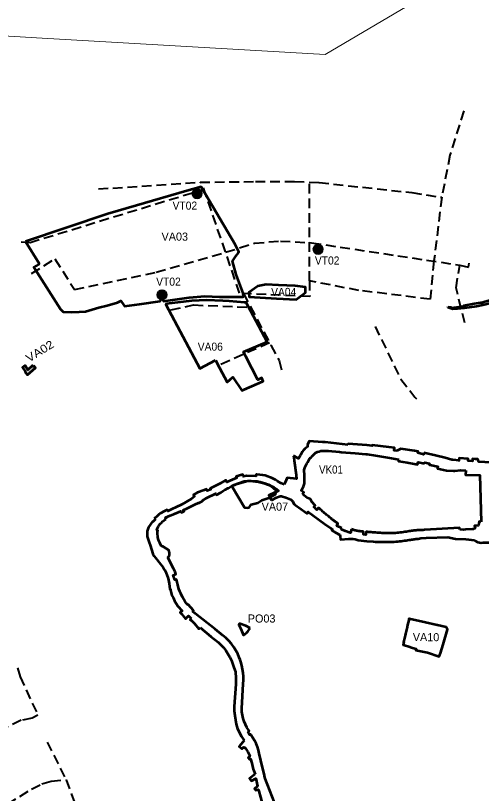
# Model space of a CAD drawing. Extents: x -650145 to -642675, y -1074338 to -1066803.
# Drawn here: x -647799 to -646647, y -1071056 to -1069131 of the extents above; entities that cross this region are included whole.
import ezdxf

# ---------------------------------------------------------------- set-up
doc = ezdxf.new("R2010")
doc.units = 0
doc.header["$LTSCALE"] = 8
doc.linetypes.add('MEDIUM_DASHED', pattern=[4.5, 3, -1.5])
for name, color, linetype, lineweight in [('12', 7, 'MEDIUM_DASHED', 40), ('15', 7, 'Continuous', 13), ('20', 7, 'Continuous', 13), ('44', 7, 'Continuous', 53), ('53', 7, 'Continuous', 53), ('55', 7, 'Continuous', 53), ('60', 7, 'Continuous', 53)]:
    doc.layers.add(name, color=color, linetype=linetype, lineweight=lineweight)
for name, color, linetype in [('17', 7, 'Continuous'), ('3', 7, 'Continuous'), ('56', 7, 'Continuous'), ('8', 7, 'Continuous')]:
    doc.layers.add(name, color=color, linetype=linetype)

msp = doc.modelspace()

# ---------------------------------------------------------------- hatches: boundary and pattern name
at = {"layer": '15'}
for points in [[(-647338.289, -1069571.583, 1), (-647361.814, -1069571.583, 1)], [(-647038.994, -1069709.305, 1), (-647062.519, -1069709.305, 1)], [(-647425.058, -1069822.133, 1), (-647448.583, -1069822.133, 1)]]:
    msp.add_hatch(color=256, dxfattribs=at).paths.add_polyline_path(points)
at = {"layer": '60'}
msp.add_hatch(color=256, dxfattribs=at).paths.add_polyline_path([(-647753.96, -1069997.9), (-647755.37, -1069999.17), (-647757.35, -1069996.96), (-647768.87, -1070007.32), (-647775.67, -1069996.86), (-647781.47, -1070001.96), (-647774.7, -1070012.64), (-647775.34, -1070013.22), (-647769.35, -1070019.98), (-647749.87, -1070002.45)])

# ---------------------------------------------------------------- linework, layer by layer
at = {"layer": '12'}
for p, q in [((-647072.241, -1069787.533), (-647072.241, -1069543.185)), ((-647291.307, -1069993.228), (-647170.84, -1069940.165)), ((-647720.463, -1070929.111), (-647674.039, -1071022.323))]:
    msp.add_line(p, q, dxfattribs=at)
for points in [[(-646690.349, -1069366.515), (-646724.478, -1069476.486), (-646744.903, -1069580.656)], [(-647594.109, -1069559.949), (-647342.265, -1069543.531), (-647205.182, -1069541.582), (-647108.806, -1069541.669), (-647047.983, -1069544.191), (-646818.857, -1069568.917), (-646744.903, -1069580.656), (-646763.998, -1069737.618), (-646773.775, -1069832.942), (-646949.668, -1069811.025), (-647072.241, -1069787.533), (-647071.353, -1069826.293), (-647244.785, -1069818.042), (-647338.767, -1069543.481)], [(-647785.07, -1069690.63), (-647763.238, -1069692.321), (-647332.905, -1069560.606)], [(-647279.5, -1069716.624), (-647208.318, -1069694.158), (-647143.504, -1069688.843), (-647066.866, -1069693.057), (-646699.975, -1069748.527), (-646678.869, -1069753.112), (-646676.91, -1069743.82)], [(-647759.613, -1069769.184), (-647701.982, -1069733.103), (-647653.087, -1069809.089), (-647451.321, -1069765.984), (-647279.5, -1069716.624)], [(-646687.702, -1069891.186), (-646709.186, -1069804.667), (-646700.4, -1069748.435)], [(-647235.467, -1069818.485), (-647167.428, -1069946.59), (-647147.296, -1069984.626), (-647140.3, -1070010.7)], [(-647414.535, -1069859.089), (-647358.559, -1069846.998), (-647217.195, -1069852.888)], [(-646909.766, -1069900.481), (-646846.095, -1070030.546), (-646811.614, -1070075.327), (-646807.189, -1070079.418)], [(-647794.16, -1070745.19), (-647787.83, -1070767.157), (-647743.987, -1070862.016), (-647758.284, -1070869.702), (-647784.836, -1070875.103), (-647850.393, -1070906.456), (-647898.698, -1070936.31), (-647903.521, -1070987.043), (-648287.54, -1071265.293)], [(-647818.707, -1071082.607), (-647759.543, -1071045.17), (-647733.735, -1071032.504), (-647710.774, -1071025.971), (-647674.039, -1071022.323), (-647646.98, -1071094.735)]]:
    msp.add_lwpolyline(points, dxfattribs=at)
at = {"layer": '15', "lineweight": 35}
for centre in [(-647350.051, -1069571.583), (-647050.756, -1069709.305), (-647436.82, -1069822.133)]:
    msp.add_circle(centre, 11.762, dxfattribs=at)
at = {"layer": '20'}
msp.add_lwpolyline([(-649263.719, -1069096.97), (-648650.963, -1069132.769), (-648341.578, -1069150.909), (-648022.16, -1069169.54), (-647733.165, -1069186.38), (-647403.931, -1069205.68), (-647033.327, -1069227.251), (-646738.287, -1069051.902)], dxfattribs=at)
at = {"layer": '44'}
msp.add_line((-646729.54, -1069853.69), (-646729.24, -1069851.41), dxfattribs=at)
for points in [[(-646515.63, -1069810.24), (-646522.32, -1069812.28), (-646560.92, -1069825.33), (-646613.65, -1069840.02), (-646620.06, -1069841.69), (-646629.83, -1069844.23), (-646635.93, -1069845.82), (-646658.5, -1069850.59), (-646689.73, -1069854.58), (-646705.87, -1069856.62), (-646717.66, -1069857.11), (-646729.54, -1069853.69)], [(-646729.24, -1069851.41), (-646723.5, -1069852.83), (-646719.82, -1069853.78), (-646689.63, -1069849.7), (-646689.8, -1069848.71), (-646664.22, -1069843.72), (-646648.18, -1069841.04), (-646648.28, -1069841.78), (-646638.34, -1069838.73), (-646623.31, -1069834.1)]]:
    msp.add_lwpolyline(points, dxfattribs=at)
at = {"layer": '53'}
msp.add_line((-647421.838, -1070473.735), (-647422.635, -1070472.518), dxfattribs=at)
for points in [[(-647039.387, -1070186.449), (-647072.923, -1070184.24), (-647076.809, -1070193), (-647076.809, -1070197.855), (-647079.337, -1070199.774), (-647083.246, -1070203.107), (-647086.798, -1070206.819), (-647089.955, -1070210.872), (-647094.562, -1070218.473), (-647099.29, -1070227.11), (-647111.87, -1070220.205)], [(-646976.875, -1070193.507), (-647032.82, -1070186.854), (-647039.387, -1070186.449)], [(-646855.781, -1070208.078), (-646862.711, -1070206.961), (-646861.74, -1070201.031), (-646875.455, -1070198.795), (-646916.636, -1070194.129), (-646916.861, -1070195.418), (-646929.734, -1070194.175), (-646930.298, -1070194.121), (-646976.601, -1070190.623), (-646976.875, -1070193.507)], [(-647111.87, -1070220.205), (-647110.98, -1070225.11), (-647110.039, -1070232.112), (-647109.285, -1070237.98)], [(-647082.83, -1070247.64), (-647081.36, -1070244.56), (-647078.582, -1070239.619), (-647076.458, -1070235.94), (-647070.915, -1070226.315), (-647067.989, -1070224.388), (-647065.283, -1070221.423), (-647064.18, -1070220.24), (-647060.499, -1070216.29), (-647056.707, -1070213.102), (-647052.28, -1070210.94), (-647047.968, -1070209.58), (-647043.59, -1070208.45), (-647035.36, -1070207.72), (-647025.027, -1070208.36), (-647016.667, -1070208.977), (-647006.834, -1070209.85), (-646997.5, -1070210.678), (-646993.691, -1070211.016), (-646958.739, -1070214.119), (-646932.512, -1070216.446), (-646929.525, -1070216.711), (-646908.791, -1070219.988), (-646868.816, -1070226.259), (-646851.139, -1070229.271)], [(-646788.988, -1070213.082), (-646789.87, -1070216.844), (-646803.79, -1070213.3), (-646802.956, -1070209.992), (-646812.428, -1070207.897), (-646845.679, -1070203.387), (-646855.781, -1070208.078)], [(-646717.674, -1070230.771), (-646719.944, -1070230.462), (-646736.508, -1070225.129), (-646760.066, -1070219.479), (-646788.988, -1070213.082)], [(-647109.285, -1070237.98), (-647106.03, -1070261.928), (-647105.074, -1070267.762), (-647104.579, -1070271.34), (-647104.079, -1070276.135), (-647104.378, -1070277.278), (-647127.044, -1070274.833), (-647131.716, -1070286.148), (-647134.186, -1070291.454)], [(-646851.139, -1070229.271), (-646851.793, -1070233.722), (-646830.617, -1070236.834), (-646813.3, -1070240.207), (-646804.487, -1070241.739), (-646803.291, -1070236.491), (-646787.53, -1070239.695)], [(-646787.53, -1070239.695), (-646786.78, -1070237.23), (-646775.43, -1070239.05), (-646775.88, -1070242.132), (-646774.542, -1070242.367), (-646754.132, -1070247.152), (-646755.192, -1070251.673), (-646732.744, -1070256.936), (-646715.68, -1070257.99), (-646712.338, -1070257.99), (-646698.729, -1070255.707), (-646685.341, -1070256.642)], [(-646593.751, -1070236.292), (-646594.226, -1070230.306), (-646619.339, -1070231.28), (-646617.731, -1070236.951), (-646623.104, -1070237.199), (-646653.044, -1070235.3), (-646655.238, -1070229.03), (-646661.949, -1070228.719), (-646668.506, -1070228.289), (-646668.854, -1070233.592), (-646679.445, -1070232.801), (-646679.103, -1070227.593), (-646701.794, -1070226.105), (-646702.125, -1070232.096), (-646702.089, -1070232.106), (-646717.674, -1070230.771)], [(-647089.327, -1070315.412), (-647086.02, -1070311.465), (-647092.921, -1070306.47), (-647090.471, -1070303.079), (-647087.003, -1070296.218), (-647085.126, -1070291.49), (-647084.541, -1070288.586), (-647084.007, -1070279.103), (-647084.542, -1070269.458), (-647085.139, -1070254.958), (-647083.753, -1070250.537), (-647082.83, -1070247.64)], [(-646685.341, -1070256.642), (-646686.113, -1070267.707), (-646650.247, -1070268.194), (-646646.892, -1070384.01)], [(-647227.638, -1070270.39), (-647235.663, -1070271.253), (-647236.556, -1070266.274), (-647252.994, -1070271.911), (-647251.55, -1070274.71), (-647268.639, -1070282.251)], [(-647134.186, -1070291.454), (-647142.537, -1070288.389), (-647151.169, -1070282.796), (-647156.431, -1070279.561), (-647165.727, -1070275.049), (-647170.603, -1070272.893), (-647175.301, -1070271.298), (-647181.491, -1070269.375), (-647187.15, -1070268.533), (-647194.921, -1070267.565), (-647202.22, -1070267.01), (-647204.18, -1070266.838), (-647204.893, -1070270.725), (-647227.638, -1070270.39)], [(-647335.663, -1070331.862), (-647336.33, -1070330.63), (-647325.666, -1070324.301), (-647303.599, -1070313.877), (-647301.753, -1070317.414), (-647291.355, -1070311.289), (-647291.55, -1070310.93), (-647285.393, -1070307.326), (-647285.626, -1070306.782), (-647280.817, -1070303.954), (-647280.52, -1070304.49), (-647274.32, -1070300.9), (-647274.046, -1070301.209), (-647263.777, -1070295.135), (-647259.22, -1070292.91), (-647256.375, -1070291.915), (-647253.6, -1070290.787), (-647224.25, -1070282.597)], [(-647292.693, -1070288.731), (-647305.843, -1070295.204), (-647317.56, -1070301.06), (-647316.143, -1070304.037), (-647324.803, -1070306.737), (-647325.346, -1070305.444)], [(-647268.639, -1070282.251), (-647276.777, -1070285.465), (-647278.788, -1070280.86), (-647292.693, -1070288.731)], [(-647224.25, -1070282.597), (-647216.198, -1070282.153), (-647201.74, -1070283.3), (-647194.11, -1070285.023), (-647182.735, -1070288.44), (-647173.41, -1070291.46), (-647165.68, -1070295.43), (-647160.5, -1070297.72), (-647154.219, -1070302.228), (-647148.592, -1070306.848), (-647171.459, -1070317.591)], [(-647325.346, -1070305.444), (-647326.68, -1070303.115), (-647332.811, -1070305.203), (-647348.647, -1070311.42), (-647359.257, -1070316.77), (-647356.197, -1070321.392), (-647364.164, -1070326.958), (-647387.944, -1070341.049), (-647403.193, -1070348.394), (-647411.024, -1070351.76), (-647422.138, -1070357.296), (-647424.173, -1070353.874), (-647430.469, -1070357.347), (-647441.048, -1070363.542), (-647444.873, -1070366.087), (-647447.25, -1070367.916), (-647455.911, -1070376.194)], [(-647045.596, -1070352.597), (-647047.32, -1070351.107), (-647048.87, -1070349.77), (-647049.568, -1070349.171), (-647054.143, -1070353.854), (-647058.429, -1070349.527), (-647060.991, -1070347.164), (-647058.157, -1070343.217), (-647066.293, -1070334.708), (-647069.397, -1070327.535), (-647077.53, -1070324.038), (-647089.327, -1070315.412)], [(-647426.277, -1070376.844), (-647427.772, -1070373.373), (-647416.229, -1070368.106), (-647406.059, -1070363.735), (-647390.119, -1070357.639), (-647388.816, -1070360.895), (-647382.324, -1070357.669), (-647384.064, -1070354.645), (-647373.332, -1070349.683), (-647355.222, -1070340.774), (-647346.673, -1070336.502), (-647345.956, -1070337.588), (-647335.663, -1070331.862)], [(-647171.459, -1070317.591), (-647172.128, -1070317.826), (-647166.107, -1070329.921)], [(-647166.107, -1070329.921), (-647153.86, -1070323.4), (-647144.45, -1070320.47), (-647141.3, -1070320.2), (-647130.2, -1070323.34), (-647118.16, -1070328.31), (-647113.43, -1070333.75), (-647110.62, -1070338.96), (-647103.17, -1070345.14), (-647097.96, -1070348.24), (-647078.044, -1070362.926), (-647075.427, -1070358.93), (-647075.165, -1070359.109)], [(-646991.821, -1070399.63), (-647004.134, -1070393.5), (-647001.683, -1070387.715), (-647003.048, -1070386.919), (-647003.754, -1070386.489), (-647004.462, -1070386.039), (-647005.194, -1070385.557), (-647005.967, -1070385.031), (-647006.797, -1070384.452), (-647007.696, -1070383.812), (-647008.673, -1070383.108), (-647009.719, -1070382.345), (-647010.83, -1070381.527), (-647012.013, -1070380.645), (-647013.28, -1070379.688), (-647014.641, -1070378.644), (-647016.107, -1070377.502), (-647017.688, -1070376.254), (-647019.391, -1070374.888), (-647021.228, -1070373.394), (-647023.206, -1070371.764), (-647025.334, -1070369.988), (-647027.584, -1070368.091), (-647029.921, -1070366.107), (-647032.305, -1070364.07), (-647034.7, -1070362.015), (-647037.07, -1070359.973), (-647039.38, -1070357.978), (-647041.593, -1070356.063), (-647043.675, -1070354.26), (-647043.687, -1070354.25), (-647045.589, -1070352.603), (-647045.596, -1070352.597)], [(-647075.165, -1070359.109), (-647035.046, -1070389.146), (-647018.999, -1070399.905), (-647016.35, -1070401.61), (-647015.31, -1070402.25), (-647016.869, -1070404.71), (-647015.647, -1070405.505)], [(-647455.911, -1070376.194), (-647453.941, -1070378.161), (-647454.569, -1070378.647), (-647459.744, -1070383.482), (-647459.98, -1070383.23), (-647470.264, -1070397.24), (-647473.142, -1070406.601), (-647473.23, -1070420.02)], [(-647448.208, -1070411.95), (-647447.956, -1070408.63), (-647447.285, -1070405.293), (-647449.792, -1070404.791), (-647448.775, -1070401.725), (-647447.342, -1070397.888), (-647445.52, -1070394.49), (-647443.39, -1070391.674), (-647441.794, -1070389.869), (-647440.112, -1070388.148), (-647438.071, -1070386.081), (-647435.424, -1070383.4), (-647432.146, -1070380.455), (-647430.002, -1070378.876), (-647428.716, -1070378.042), (-647427.576, -1070377.411), (-647426.277, -1070376.844)], [(-646646.892, -1070384.01), (-646652.452, -1070383.215), (-646653.681, -1070392.621), (-646663.728, -1070393.386), (-646662.591, -1070396.445), (-646661.883, -1070399.33), (-646664.023, -1070400.625), (-646666.336, -1070401.577), (-646668.768, -1070402.162), (-646686.006, -1070403.039)], [(-647433.32, -1070445.47), (-647438.589, -1070443.564), (-647442.35, -1070435.926), (-647445.384, -1070429.078), (-647447.459, -1070422.162), (-647448.208, -1070411.95)], [(-647015.647, -1070405.505), (-647007.956, -1070410.529), (-646996.499, -1070416.186)], [(-646967.84, -1070401.852), (-646970.441, -1070410.852), (-646970.98, -1070410.71), (-646983.029, -1070407.174), (-646992.643, -1070403.03), (-646991.821, -1070399.63)], [(-646828.906, -1070407.862), (-646832.375, -1070408.403), (-646835.976, -1070408.955), (-646839.69, -1070409.505), (-646843.502, -1070410.038), (-646847.398, -1070410.541), (-646851.361, -1070411.001), (-646855.373, -1070411.404), (-646859.416, -1070411.737), (-646863.477, -1070411.987), (-646867.57, -1070412.148), (-646871.709, -1070412.226), (-646875.882, -1070412.227), (-646880.074, -1070412.163), (-646884.267, -1070412.04), (-646888.447, -1070411.868), (-646892.598, -1070411.657), (-646896.705, -1070411.416), (-646900.755, -1070411.154), (-646904.73, -1070410.882), (-646908.607, -1070410.608), (-646912.37, -1070410.335), (-646916.014, -1070410.063), (-646919.538, -1070409.792), (-646922.942, -1070409.521), (-646926.223, -1070409.252), (-646929.38, -1070408.982), (-646931.651, -1070408.781), (-646932.258, -1070415.651), (-646938.546, -1070415.207), (-646938.092, -1070408.178), (-646940.732, -1070407.911), (-646943.231, -1070407.644), (-646945.59, -1070407.374), (-646947.808, -1070407.099), (-646949.885, -1070406.818), (-646951.821, -1070406.53), (-646953.614, -1070406.234), (-646955.264, -1070405.93), (-646956.768, -1070405.619), (-646958.13, -1070405.3), (-646959.38, -1070404.97), (-646960.562, -1070404.622), (-646961.711, -1070404.248), (-646962.856, -1070403.845), (-646964.026, -1070403.405), (-646965.244, -1070402.924), (-646966.531, -1070402.398), (-646967.84, -1070401.852)], [(-646700.237, -1070403.062), (-646700.989, -1070398.597), (-646786.341, -1070403.956), (-646787.341, -1070403.977), (-646790.547, -1070404.058), (-646793.665, -1070404.156), (-646796.692, -1070404.277), (-646799.623, -1070404.427), (-646802.474, -1070404.607), (-646805.269, -1070404.82), (-646808.036, -1070405.068), (-646810.799, -1070405.352), (-646813.587, -1070405.672), (-646816.428, -1070406.031), (-646819.35, -1070406.428), (-646822.385, -1070406.865), (-646825.565, -1070407.344), (-646828.894, -1070407.86), (-646828.906, -1070407.862)], [(-646686.006, -1070403.039), (-646691.689, -1070403.329), (-646699.257, -1070403.03), (-646700.237, -1070403.062)], [(-647473.23, -1070420.02), (-647468.3, -1070435.07), (-647466.18, -1070441.43), (-647459.874, -1070462.861), (-647456.2, -1070468.57), (-647437.261, -1070492.674), (-647434.05, -1070496.76), (-647430.826, -1070502.451)], [(-646996.499, -1070416.186), (-646996.083, -1070419.677), (-646994.969, -1070427.882), (-646974.446, -1070425.718), (-646965.002, -1070426.073), (-646959.178, -1070427.144), (-646951.615, -1070428.872), (-646930.243, -1070431.622), (-646914.815, -1070432.88), (-646909.554, -1070432.972), (-646904.483, -1070433.289), (-646889.217, -1070433.283), (-646876.04, -1070433.228), (-646871.508, -1070433.225), (-646866.962, -1070433.141), (-646862.418, -1070432.962), (-646857.907, -1070432.683), (-646853.462, -1070432.317), (-646849.102, -1070431.879), (-646844.844, -1070431.386), (-646840.704, -1070430.851), (-646836.699, -1070430.291), (-646832.847, -1070429.721), (-646829.165, -1070429.156), (-646825.675, -1070428.612)], [(-646825.674, -1070428.612), (-646822.393, -1070428.103), (-646819.324, -1070427.641), (-646816.437, -1070427.225), (-646813.698, -1070426.853), (-646811.073, -1070426.522), (-646808.528, -1070426.229), (-646806.026, -1070425.972), (-646803.533, -1070425.749), (-646796.661, -1070424.439), (-646783.408, -1070423.561)], [(-646783.408, -1070423.561), (-646730.097, -1070421.861), (-646711.012, -1070425.553), (-646685.466, -1070426.561), (-646664.091, -1070429.494)], [(-646664.091, -1070429.494), (-646660.264, -1070432.064), (-646656.068, -1070433.973), (-646651.616, -1070435.17), (-646647.029, -1070435.621), (-646642.429, -1070435.315), (-646637.107, -1070434.832), (-646632.649, -1070434.654), (-646628.195, -1070434.931), (-646623.793, -1070435.659), (-646612.723, -1070438.074), (-646607.615, -1070438.944), (-646602.448, -1070439.34), (-646597.266, -1070439.257)], [(-647422.635, -1070472.518), (-647421.264, -1070471.257), (-647420.114, -1070469.791), (-647419.216, -1070468.16), (-647418.594, -1070466.404), (-647418.263, -1070464.571), (-647418.232, -1070462.709), (-647418.502, -1070460.866), (-647420.106, -1070453.908), (-647433.32, -1070445.47)], [(-647224.617, -1070903.278), (-647221.501, -1070901.282), (-647226.886, -1070892.878), (-647230.583, -1070885.59), (-647233.667, -1070878.022), (-647236.118, -1070870.225), (-647237.918, -1070862.254), (-647239.056, -1070854.161), (-647239.525, -1070846.002), (-647236.091, -1070784.561), (-647235.55, -1070775.461), (-647235.59, -1070766.345), (-647236.21, -1070757.25), (-647237.409, -1070748.213), (-647239.181, -1070739.271), (-647241.519, -1070730.46), (-647243.113, -1070725.123), (-647245.528, -1070719.71), (-647249.533, -1070710.712), (-647254.176, -1070702.027), (-647259.433, -1070693.699), (-647265.276, -1070685.771), (-647271.675, -1070678.285), (-647278.597, -1070671.28), (-647286.007, -1070664.792), (-647305.469, -1070649.314), (-647354.984, -1070610.424), (-647360.3, -1070605.96), (-647358.52, -1070603.139), (-647371.668, -1070588.064), (-647373.213, -1070589.463), (-647376.365, -1070585.615), (-647379.166, -1070581.773), (-647383.179, -1070575.705), (-647386.317, -1070570.266), (-647390.581, -1070561.567), (-647392.902, -1070556.038), (-647394.81, -1070550.354), (-647397.865, -1070539.885), (-647401.25, -1070526.421), (-647404.957, -1070527.663), (-647408.928, -1070515.558), (-647402.42, -1070512.979), (-647404.443, -1070507.876), (-647408.443, -1070499.138), (-647421.838, -1070473.735)], [(-647430.826, -1070502.451), (-647430.175, -1070503.595), (-647427.37, -1070508.543), (-647421.363, -1070524.033), (-647418.728, -1070536.26)], [(-647418.728, -1070536.26), (-647417.463, -1070550.662), (-647415.753, -1070550.54), (-647415.668, -1070552.865), (-647412.127, -1070565.842), (-647409.341, -1070571.096), (-647405.495, -1070579.324), (-647397.6, -1070592.644), (-647387.203, -1070604.308), (-647391.88, -1070608.543), (-647388.807, -1070611.935), (-647378.252, -1070623.591), (-647371.261, -1070616.372), (-647364.451, -1070623.134)], [(-647364.451, -1070623.134), (-647367.307, -1070626.671), (-647362.582, -1070628.813), (-647356.04, -1070635.757), (-647345.348, -1070648.477), (-647342.717, -1070645.267)], [(-647342.717, -1070645.267), (-647315.939, -1070667.498), (-647298.155, -1070681.741), (-647291.137, -1070688.056), (-647284.675, -1070694.939), (-647278.816, -1070702.343), (-647273.602, -1070710.213), (-647269.069, -1070718.495), (-647265.249, -1070727.129), (-647259.003, -1070744.385), (-647254.86, -1070755.5)], [(-647254.86, -1070755.5), (-647254.424, -1070770.54), (-647254.519, -1070785.586), (-647258.505, -1070840.521), (-647257.977, -1070851.738), (-647256.874, -1070862.913), (-647255.2, -1070874.017), (-647252.958, -1070885.021), (-647250.155, -1070895.895), (-647240.065, -1070915.49), (-647236.98, -1070920.1), (-647233.29, -1070925.28)], [(-647158.755, -1071078.706), (-647175.93, -1071034.15), (-647179.458, -1071025.505), (-647182.273, -1071016.602), (-647184.357, -1071007.501), (-647188.273, -1070991.778), (-647196.024, -1070957.071), (-647198.121, -1070948.772), (-647200.829, -1070940.652), (-647204.133, -1070932.756), (-647208.015, -1070925.127), (-647215.994, -1070911.999), (-647217.751, -1070909.109), (-647220.159, -1070911.092), (-647224.617, -1070903.278)], [(-647233.29, -1070925.28), (-647245.612, -1070939.528), (-647238.512, -1070945.802), (-647235.078, -1070941.916), (-647234.883, -1070941.8), (-647233.638, -1070942.177), (-647232.47, -1070942.748), (-647231.407, -1070943.498), (-647230.478, -1070944.409), (-647229.706, -1070945.455), (-647224.246, -1070953.437), (-647220.4, -1070961.767), (-647219.494, -1070964.147), (-647223.659, -1070967.863), (-647220.226, -1070972.022), (-647217.601, -1070970.436), (-647214.881, -1070981.551), (-647212.031, -1070992.32), (-647211.174, -1070995.794), (-647206.4, -1071008.143)], [(-647206.4, -1071008.143), (-647220.075, -1071019.169), (-647215.715, -1071024.528), (-647204.286, -1071019.233), (-647200.697, -1071038.069), (-647208.059, -1071044.509), (-647205.591, -1071047.733), (-647198.635, -1071046.314), (-647197.667, -1071050.39), (-647193.273, -1071065.367), (-647190.333, -1071074.194), (-647187.306, -1071082.342), (-647183.964, -1071090.241), (-647191.246, -1071093.802), (-647187.936, -1071100.378), (-647180.976, -1071097.304), (-647179.761, -1071100.174), (-647168.392, -1071123.89), (-647168.218, -1071124.182)]]:
    msp.add_lwpolyline(points, dxfattribs=at)
at = {"layer": '55'}
for points in [[(-647218.44, -1070647.43), (-647229.34, -1070640.91), (-647243.28, -1070636.43), (-647245.6, -1070636.4), (-647246.49, -1070638.53), (-647241.89, -1070648.94)], [(-647241.89, -1070648.94), (-647237.61, -1070658.33), (-647235.02, -1070664.1), (-647227.76, -1070658.33)], [(-647227.76, -1070658.33), (-647224.57, -1070655.48), (-647224.37, -1070655.59), (-647218.44, -1070647.43)]]:
    msp.add_lwpolyline(points, dxfattribs=at)
at = {"layer": '60'}
for points in [[(-647774.11, -1069689.64), (-647740.74, -1069744.24), (-647742.36, -1069746.93), (-647753.7, -1069753.9), (-647745.84, -1069766.71), (-647687.45, -1069857.15), (-647681.51, -1069863.72), (-647661.79, -1069864.92), (-647641.78, -1069864.26), (-647625.83, -1069863.19), (-647593.07, -1069853.74), (-647572.63, -1069848.63), (-647547.12, -1069840.87), (-647538.34, -1069836.68), (-647531.33, -1069847.23), (-647529.5, -1069849.99), (-647492.76, -1069845.02), (-647441.19, -1069837.6), (-647437.46, -1069832.27), (-647433.32, -1069837.33), (-647369.3, -1069828.22), (-647330.46, -1069825.51), (-647294.38, -1069826.88), (-647270.09, -1069827.02), (-647253.88, -1069827.12), (-647236.5, -1069826.63), (-647235.49, -1069826.51), (-647235.62, -1069817.62), (-647253.45, -1069771.95), (-647262.46, -1069738.25), (-647253.97, -1069726.27), (-647247.86, -1069717.66), (-647246.42, -1069715.63), (-647256.061, -1069697.32), (-647339.58, -1069554.46), (-647375.71, -1069564.91), (-647499.63, -1069600.73), (-647570.37, -1069621.18)], [(-647178.73, -1069796.4), (-647199.65, -1069800.69), (-647221.87, -1069816.21), (-647221.14, -1069826.761), (-647153.36, -1069830.79), (-647104.741, -1069833.568), (-647082.145, -1069816.321), (-647082.206, -1069802.916), (-647107.04, -1069799.84), (-647148.9, -1069797.88)], [(-647304.05, -1069983.79), (-647294.257, -1070002.745), (-647276, -1070038.08), (-647261.27, -1070026.12), (-647238.99, -1070059.05), (-647195.933, -1070040.107), (-647186.148, -1070035.802), (-647186.4, -1070035.27), (-647189.83, -1070027.59), (-647199.984, -1070032.112), (-647229.096, -1069974.658), (-647235, -1069963), (-647176.499, -1069938.333), (-647217.177, -1069862.57), (-647228.77, -1069840.98), (-647232.66, -1069841.07), (-647270.71, -1069837.61), (-647285.9, -1069836.66), (-647326.71, -1069835.46), (-647363.21, -1069836.64), (-647425.73, -1069844.31), (-647427.62, -1069845.94), (-647413.461, -1069872.442), (-647342.93, -1070004.49)], [(-647753.96, -1069997.9), (-647755.37, -1069999.17), (-647757.35, -1069996.96), (-647768.87, -1070007.32), (-647775.67, -1069996.86), (-647781.47, -1070001.96), (-647774.7, -1070012.64), (-647775.34, -1070013.22), (-647769.35, -1070019.98), (-647749.87, -1070002.45)], [(-647219.36, -1070283.36), (-647233.82, -1070284.22), (-647259.22, -1070292.91), (-647263.72, -1070295.43), (-647232.55, -1070348.65), (-647226.24, -1070348.88), (-647220.9, -1070348.04), (-647216.16, -1070340.99), (-647199.79, -1070337.21), (-647189.63, -1070330.53), (-647167.43, -1070322.66), (-647155.89, -1070316.51), (-647154.23, -1070306.63), (-647167.15, -1070295.69), (-647184.77, -1070288.73), (-647197.68, -1070285.3)], [(-646825.54, -1070624.03), (-646826.12, -1070623.9), (-646826.45, -1070627.3), (-646827.98, -1070632.83), (-646828.22, -1070632.77), (-646829.55, -1070638.78), (-646829.55, -1070638.78), (-646829.3, -1070638.83), (-646830.51, -1070644.3), (-646830.26, -1070644.35), (-646832.46, -1070654.31), (-646832.7, -1070654.26), (-646834.27, -1070661.39), (-646834.27, -1070661.39), (-646834.4, -1070661.35), (-646835.23, -1070665.08), (-646835.1, -1070665.12), (-646836.6, -1070671.54), (-646836.6, -1070671.54), (-646836.87, -1070671.46), (-646839.27, -1070681.62), (-646838.96, -1070681.72), (-646840.36, -1070687.86), (-646828.7, -1070691.73), (-646816.84, -1070695.43), (-646808.09, -1070698.19), (-646808.76, -1070701.11), (-646780.44, -1070707.59), (-646751.23, -1070717), (-646748.04, -1070709.23), (-646741.52, -1070687.22), (-646730.66, -1070650.07), (-646734.18, -1070644.6), (-646755.21, -1070639.87), (-646755.84, -1070639.88), (-646784.62, -1070633.19)]]:
    msp.add_lwpolyline(points, close=True, dxfattribs=at)

# ---------------------------------------------------------------- texts
at = {"layer": '17', "width": 0.95}
for p in [(-647410.59, -1069611.16), (-647058.579, -1069746.971), (-647451.166, -1069799.33)]:
    msp.add_text('VT02', height=20, dxfattribs=at).set_placement(p)
at = {"layer": '3'}
for s, p in [('VA03', (-647437.904, -1069687.886)), ('VA07', (-647190.33, -1070356.214))]:
    msp.add_text(s, height=20, dxfattribs=at).set_placement(p)
at = {"layer": '3', "width": 0.95}
for s, p in [('VA04', (-647166.855, -1069824.823)), ('VA06', (-647348.354, -1069960.268))]:
    msp.add_text(s, height=20, dxfattribs=at).set_placement(p)
at = {"layer": '3', "width": 1.15}
msp.add_text('VA02', height=20, rotation=31.795, dxfattribs=at).set_placement((-647765.887, -1069989.737))
at = {"layer": '3'}
msp.add_text('VA10', height=20, rotation=359.629, dxfattribs=at).set_placement((-646816.427, -1070678.964))
at = {"layer": '56'}
msp.add_text('PO03', height=20, dxfattribs=at).set_placement((-647224.547, -1070633.139))
at = {"layer": '8', "width": 0.9}
msp.add_text('VK01', height=20, dxfattribs=at).set_placement((-647048.265, -1070264.389))

doc.saveas('drawing.dxf')
